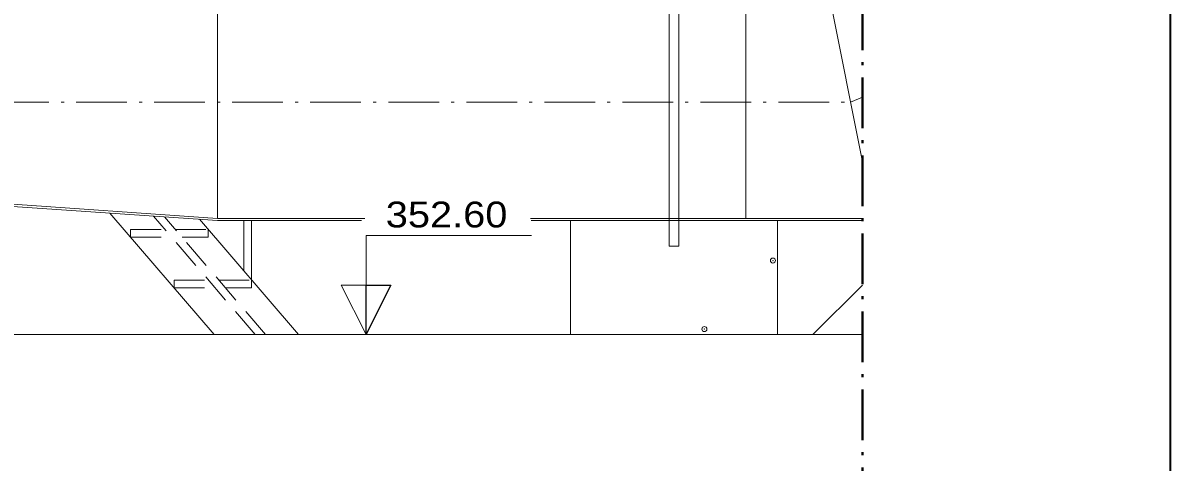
# Model space of a CAD drawing. Extents: x -4160 to -2690, y -474 to 714.
# Drawn here: x -3604.2 to -3540.8, y -403.6 to -379.3 of the extents above; entities that cross this region are included whole.
import ezdxf
from ezdxf.enums import TextEntityAlignment as Align

# ---------------------------------------------------------------- set-up
doc = ezdxf.new("R2010")
doc.units = 0
doc.header["$LTSCALE"] = 0.56
doc.header["$PDMODE"] = 32
doc.header["$PDSIZE"] = 0.28
doc.linetypes.add('DOT_DASHED', pattern=[7.7, 5, -1.2, 0.3, -1.2])
doc.linetypes.add('MEDIUM_DASHED', pattern=[4.5, 3, -1.5])
for name, color, linetype, lineweight in [('10', 7, 'Continuous', 35), ('11', 7, 'Continuous', 13), ('12', 7, 'Continuous', 13), ('14', 7, 'Continuous', 13), ('17', 7, 'Continuous', 13), ('2', 7, 'Continuous', 25), ('24', 7, 'Continuous', 13), ('5', 7, 'Continuous', 35), ('63', 7, 'Continuous', 13), ('9', 7, 'Continuous', 13)]:
    doc.layers.add(name, color=color, linetype=linetype, lineweight=lineweight)

msp = doc.modelspace()

# ---------------------------------------------------------------- linework, layer by layer
at = {"layer": '10', "lineweight": 13}
for p, q in [((-3599.3528, -389.8483), (-3593.5899, -396.5725)), ((-3594.4071, -390.1897), (-3588.9371, -396.5725)), ((-3591.9485, -390.2583), (-3591.9485, -393.0583)), ((-3591.5199, -393.5583), (-3591.5199, -390.2583))]:
    msp.add_line(p, q, dxfattribs=at)
at = {"layer": '10', "linetype": 'MEDIUM_DASHED', "lineweight": 13}
for p, q in [((-3591.3156, -396.5725), (-3596.9356, -390.0154)), ((-3590.7513, -396.5725), (-3596.3356, -390.0568)), ((-3598.2056, -390.7583), (-3596.2985, -390.7583)), ((-3598.2056, -390.7583), (-3598.2056, -391.1868)), ((-3595.7342, -390.7583), (-3593.9199, -390.7583)), ((-3593.9199, -390.7583), (-3593.9199, -391.1868)), ((-3598.2056, -391.1868), (-3595.9313, -391.1868)), ((-3595.3671, -391.1868), (-3593.9199, -391.1868)), ((-3595.8056, -393.5583), (-3595.8056, -393.9868)), ((-3595.8056, -393.5583), (-3593.8985, -393.5583)), ((-3593.3342, -393.5583), (-3591.5199, -393.5583)), ((-3591.5199, -393.5583), (-3591.5199, -393.9868)), ((-3595.8056, -393.9868), (-3593.5313, -393.9868)), ((-3592.9671, -393.9868), (-3591.5199, -393.9868))]:
    msp.add_line(p, q, dxfattribs=at)
at = {"layer": '11'}
for p, q in [((-3573.8899, -390.2583), (-3573.8899, -396.5725)), ((-3562.4614, -390.2583), (-3562.4614, -396.5725)), ((-3668.1756, -396.5725), (-3573.8899, -396.5725)), ((-3562.4614, -396.5725), (-3557.7642, -396.5725))]:
    msp.add_line(p, q, dxfattribs=at)
at = {"layer": '12'}
msp.add_line((-3573.8899, -396.5725), (-3562.4614, -396.5725), dxfattribs=at)
at = {"layer": '14'}
for p in [(-3562.7128, -392.474), (-3566.5014, -396.2611)]:
    msp.add_point(p, dxfattribs=at)
at = {"layer": '17'}
msp.add_line((-3560.5085, -396.5725), (-3557.7642, -393.8283), dxfattribs=at)
at = {"layer": '2'}
msp.add_line((-3585.1941, -396.5726), (-3583.8227, -393.8298), dxfattribs=at)
msp.add_lwpolyline([(-3585.1941, -396.5726), (-3585.1941, -393.8298), (-3583.8227, -393.8298)], close=True, dxfattribs=at)
at = {"layer": '24'}
for p, q in [((-3568.4442, -375.744), (-3568.4442, -391.6868)), ((-3567.9085, -375.744), (-3567.9085, -391.6868)), ((-3564.2042, -377.1726), (-3564.2042, -390.144)), ((-3593.4099, -377.2868), (-3593.4099, -390.144)), ((-3559.6957, -377.2868), (-3557.7642, -387.0083)), ((-3607.6956, -389.1583), (-3593.4099, -390.144)), ((-3607.6999, -389.2725), (-3593.4142, -390.2583)), ((-3593.4142, -390.2583), (-3585.4528, -390.2583)), ((-3593.4099, -390.144), (-3585.2571, -390.144)), ((-3576.1128, -390.144), (-3564.2042, -390.144)), ((-3576.0642, -390.2583), (-3564.2042, -390.2583)), ((-3564.2042, -390.144), (-3557.7642, -390.144)), ((-3564.2042, -390.2583), (-3557.7642, -390.2583)), ((-3568.4442, -391.6868), (-3567.9085, -391.6868))]:
    msp.add_line(p, q, dxfattribs=at)
at = {"layer": '5', "linetype": 'DOT_DASHED', "lineweight": 13}
for p, q in [((-3558.4213, -383.7155), (-3557.7642, -383.4426)), ((-3627.0841, -383.7155), (-3558.4213, -383.7155))]:
    msp.add_line(p, q, dxfattribs=at)
at = {"layer": '5'}
msp.add_lwpolyline([(-3714.764, -463.5197), (-3714.764, -210.5199), (-3540.7642, -210.5199), (-3540.7642, -463.5197)], close=True, dxfattribs=at)
at = {"layer": '63'}
for p, q in [((-3585.1942, -391.0868), (-3576.0514, -391.0868)), ((-3585.1942, -393.8297), (-3585.1942, -391.0868)), ((-3586.5656, -393.8297), (-3585.1942, -396.5725)), ((-3583.8228, -393.8297), (-3586.5656, -393.8297)), ((-3585.1942, -396.5725), (-3583.8228, -393.8297)), ((-3562.4614, -396.5725), (-3557.7642, -396.5725))]:
    msp.add_line(p, q, dxfattribs=at)
at = {"layer": '9', "linetype": 'DOT_DASHED', "lineweight": 40}
msp.add_line((-3557.7642, -244.3684), (-3557.7642, -446.0525), dxfattribs=at)

# ---------------------------------------------------------------- texts
at = {"layer": '2', "width": 1.15}
msp.add_text('352.60', height=1.429, dxfattribs=at).set_placement((-3580.7463, -390.644), align=Align.CENTER)

doc.saveas('drawing.dxf')
